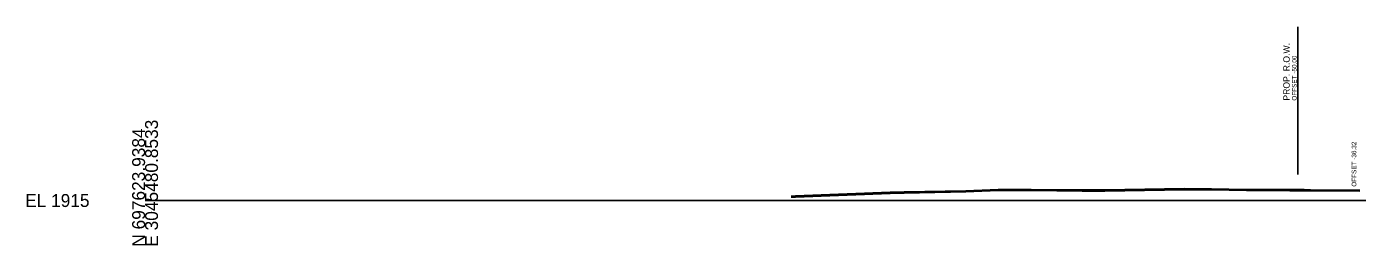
# Model space of a CAD drawing. Extents: x 1574 to 14903, y 7971 to 16537.
# Drawn here: x 12674.3 to 12962.9, y 7990.3 to 8037.6 of the extents above; entities that cross this region are included whole.
import ezdxf

# ---------------------------------------------------------------- set-up
doc = ezdxf.new("R2010")
doc.units = 0
for name, color, linetype in [('DESIGN - ROW - Right-of-Way and Easement Labels', 7, 'Continuous'), ('DESIGN - ROW - Right-of-Way Linework', 7, 'Continuous'), ('DESIGN - SHEET - Light Grid', 7, 'Continuous'), ('DESIGN - TYPICAL - Slope Tie Text', 7, 'Continuous'), ('SURVEY - GROUND - Bottom of Topsoil Layer', 7, 'Continuous'), ('SURVEY - GROUND - Top of Ground', 7, 'Continuous')]:
    doc.layers.add(name, color=color, linetype=linetype)

msp = doc.modelspace()

# ---------------------------------------------------------------- linework, layer by layer
at = {"layer": 'DESIGN - ROW - Right-of-Way Linework'}
msp.add_line((12950, 8005.61), (12950, 8037.61), dxfattribs=at)
at = {"layer": 'DESIGN - SHEET - Light Grid'}
msp.add_line((12700, 8000), (13000, 8000), dxfattribs=at)
at = {"layer": 'SURVEY - GROUND - Bottom of Topsoil Layer'}
for p, q in [((12840.13, 8000.72), (12841.03, 8000.73)), ((12841.03, 8000.73), (12861.57, 8001.53)), ((12861.57, 8001.53), (12864.61, 8001.61)), ((12864.61, 8001.61), (12878.04, 8001.87)), ((12878.04, 8001.87), (12885.04, 8002.15)), ((12885.04, 8002.15), (12888.83, 8002.15)), ((12888.83, 8002.15), (12892.14, 8002.14)), ((12892.14, 8002.14), (12903.26, 8002.03)), ((12903.26, 8002.03), (12908.15, 8002.06)), ((12908.15, 8002.06), (12925.43, 8002.33)), ((12925.43, 8002.33), (12931.32, 8002.3)), ((12931.32, 8002.3), (12938.87, 8002.17)), ((12938.87, 8002.17), (12948.26, 8002.12)), ((12948.26, 8002.12), (12949.8, 8002.11)), ((12949.8, 8002.11), (12951.35, 8002.1)), ((12951.35, 8002.1), (12952.75, 8002.07)), ((12952.75, 8002.07), (12963.44, 8001.99))]:
    msp.add_line(p, q, dxfattribs=at)
at = {"layer": 'SURVEY - GROUND - Top of Ground'}
msp.add_lwpolyline([(12840.13, 8000.97), (12841.03, 8000.98), (12861.57, 8001.78), (12864.61, 8001.86), (12878.04, 8002.12), (12885.04, 8002.4), (12888.83, 8002.4), (12892.14, 8002.39), (12903.26, 8002.28), (12908.15, 8002.31), (12925.43, 8002.58), (12931.32, 8002.55), (12938.87, 8002.42), (12948.26, 8002.37), (12949.8, 8002.36), (12951.35, 8002.35), (12952.75, 8002.32), (12963.44, 8002.24)], dxfattribs=at)

# ---------------------------------------------------------------- texts
at = {"layer": 'DESIGN - ROW - Right-of-Way and Easement Labels'}
for s, height, p in [('PROP. R.O.W.', 1.4, (12948.25, 8021.61)), ('OFFSET -50.00', 1, (12949.75, 8021.61))]:
    msp.add_text(s, height=height, rotation=90, dxfattribs=at).set_placement(p)
at = {"layer": 'DESIGN - SHEET - Light Grid'}
for s, p in [('N 697623.9384', (12700, 7990)), ('E 3045480.8533', (12702.8, 7990))]:
    msp.add_text(s, height=2.8, rotation=90, dxfattribs=at).set_placement(p)
msp.add_text('EL 1915', height=2.8, dxfattribs=at).set_placement((12674, 7998.6))
at = {"layer": 'DESIGN - TYPICAL - Slope Tie Text'}
msp.add_text('OFFSET -36.32', height=1, rotation=90, dxfattribs=at).set_placement((12962.69, 8002.99))

doc.saveas('drawing.dxf')
